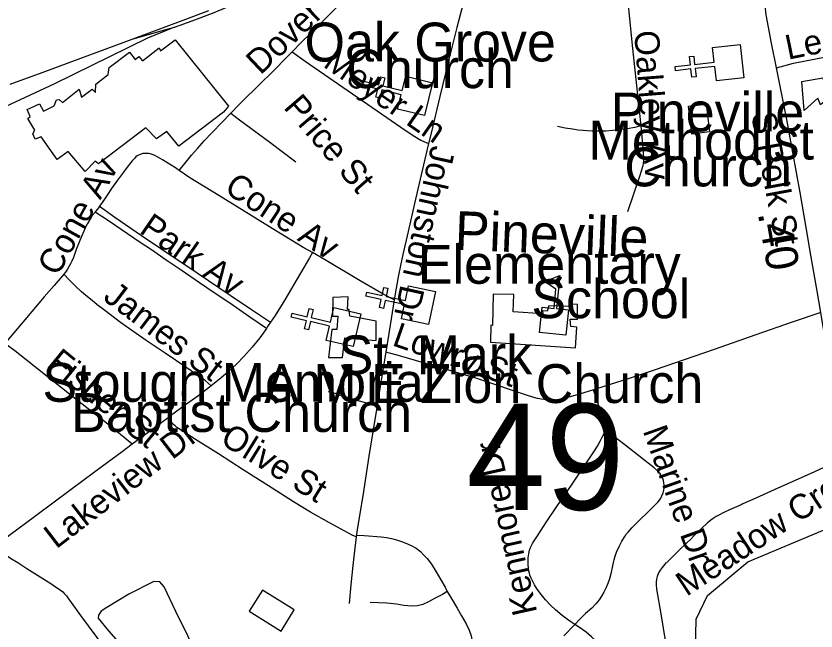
# Model space of a CAD drawing. Extents: x 1383679 to 1536984, y 460658 to 651027.
# Drawn here: x 1432722 to 1435810, y 488802 to 491178 of the extents above; entities that cross this region are included whole.
import ezdxf

# ---------------------------------------------------------------- set-up
doc = ezdxf.new("R2010")
doc.units = 0
for name, color, linetype in [('Exist Cultural Church CELL', 7, 'Continuous'), ('Exist Cultural Church Label', 7, 'Continuous'), ('Exist Cultural Educational Facility Elementary CELL', 7, 'Continuous'), ('Exist Cultural Educational Facility High Label', 7, 'Continuous'), ('Exist Cultural Warehouse Building Footprint', 7, 'Continuous'), ('Exist Hydrographic Creek Single Shore', 7, 'Continuous'), ('Exist Hydrographic Misc Water Feature', 7, 'Continuous'), ('Exist Railroad Mainline', 7, 'Continuous'), ('Exist Railroad Spur', 7, 'Continuous'), ('Exist Road Non-System Type 51', 7, 'Continuous'), ('Exist Road Non-System Type 51 Label', 7, 'Continuous'), ('Exist Road Secondary Mileage Hundredths English Label', 7, 'Continuous'), ('Exist Road Secondary Structure Standard Bridge Number Label', 7, 'Continuous'), ('Exist Road Secondary Type 51 Attributed', 7, 'Continuous'), ('Exist Road Secondary Type 51 Label', 7, 'Continuous')]:
    doc.layers.add(name, color=color, linetype=linetype)

msp = doc.modelspace()

# ---------------------------------------------------------------- linework, layer by layer
at = {"layer": 'Exist Cultural Church CELL'}
for points in [[(1435425.1, 490926.5), (1435418.7, 490983), (1435343, 490974.6), (1435346.5, 490942.8), (1435330.6, 490941.1), (1435327.1, 490972.9), (1435267.3, 490966.2), (1435265.6, 490982.2), (1435325.3, 490988.8), (1435321.8, 491020.6), (1435337.7, 491022.4), (1435341.2, 490990.6), (1435416.9, 490999), (1435410.6, 491056.3), (1435516.4, 491068), (1435530.9, 490938.2)], [(1434195, 490818.2), (1434208.4, 490873.6), (1434134.5, 490891.7), (1434126.9, 490860.6), (1434111.4, 490864.4), (1434119, 490895.5), (1434060.5, 490909.8), (1434064.3, 490925.3), (1434122.8, 490911), (1434130.4, 490942.1), (1434145.9, 490938.3), (1434138.3, 490907.2), (1434212.2, 490889.1), (1434226.1, 490945.1), (1434329.5, 490919.8), (1434298.4, 490792.9)], [(1434209.8, 490007.5), (1434221.4, 490063.2), (1434147, 490079), (1434140.3, 490047.7), (1434124.7, 490051), (1434131.3, 490082.3), (1434072.5, 490094.7), (1434075.8, 490110.4), (1434134.7, 490097.9), (1434141.3, 490129.3), (1434156.9, 490125.9), (1434150.3, 490094.6), (1434224.8, 490078.8), (1434236.8, 490135.2), (1434341, 490113.2), (1434313.9, 489985.4)], [(1433919.7, 489924.3), (1433932.4, 489979.8), (1433858.2, 489996.9), (1433851, 489965.7), (1433835.4, 489969.3), (1433842.6, 490000.5), (1433784, 490014), (1433787.6, 490029.6), (1433846.2, 490016.1), (1433853.4, 490047.3), (1433869, 490043.7), (1433861.8, 490012.5), (1433936, 489995.4), (1433949, 490051.5), (1434052.8, 490027.6), (1434023.4, 489900.3)]]:
    msp.add_lwpolyline(points, close=True, dxfattribs=at)
at = {"layer": 'Exist Cultural Educational Facility Elementary CELL'}
msp.add_lwpolyline([(1434743, 489955.3), (1434752.8, 490052.7), (1434798.6, 490048.1), (1434806, 490122.8), (1434761.6, 490151.6), (1434820.9, 490175), (1434808.1, 490047.2), (1434853.9, 490042.6), (1434844.2, 489945.1)], close=True, dxfattribs=at)
at = {"layer": 'Exist Cultural Warehouse Building Footprint'}
for points in [[(1433522.8, 490805.8), (1433350.2, 490674.6), (1433304.3, 490732), (1433264.5, 490702.7), (1433223.4, 490746.1), (1433041.1, 490606.7), (1433027.9, 490617.2), (1432989.2, 490576.3), (1432924, 490653.6), (1432880.6, 490623.1), (1432819, 490710.9), (1432796.1, 490701.6), (1432786.4, 490722.7), (1432794.8, 490736.7), (1432767.1, 490781.2), (1432776.7, 490789.4), (1432764.7, 490816.3), (1432813, 490838.6), (1432828.7, 490809.3), (1432869.7, 490830.4), (1432878.2, 490853.8), (1432889, 490855), (1432901.1, 490843.3), (1432966.3, 490894.8), (1432974.7, 490864.4), (1433015.8, 490894.8), (1433029.1, 490881.9), (1433030.3, 490913.6), (1433077.4, 490951), (1433081, 490979.1), (1433160.7, 491037.7), (1433182.4, 491009.6), (1433195.7, 491021.3), (1433210.2, 491004.9), (1433274.1, 491054.1), (1433280.2, 491043.6), (1433336.9, 491085.7), (1433542.2, 490829.2), (1433522.8, 490805.8)], [(1435755.1, 490924.1), (1435836, 490938.2), (1435854.1, 490857.3), (1435826.4, 490833.9), (1435816.7, 490859.7), (1435763.6, 490812.8), (1435755.1, 490924.1)], [(1435316.9, 490828.6), (1435385.5, 490837.3), (1435399, 490730.3), (1435330.3, 490721.6), (1435316.9, 490828.6)], [(1433945.4, 490090.8), (1433943, 490018.2), (1433964.7, 490018.2), (1433959.9, 489966.6), (1433940.6, 489966.6), (1433928.5, 489858.9), (1433981.6, 489858.9), (1433991.3, 489933.8), (1434112, 489924.5), (1434112, 489999.4), (1434010.6, 490018.2), (1434008.2, 490043.9), (1434000.9, 490043.9), (1434003.4, 490093.1), (1433945.4, 490090.8)], [(1434563.5, 490103.7), (1434561.1, 489981.9), (1434555.1, 489983), (1434553.9, 489917.5), (1434881.1, 489896.4), (1434885.9, 489976), (1434862.9, 489978.4), (1434860.5, 490006.5), (1434889.5, 490006.5), (1434889.5, 490062.7), (1434858.1, 490065), (1434859.3, 490055.7), (1434778.4, 490058), (1434772.4, 490036.9), (1434754.3, 490038.1), (1434755.5, 490027.5), (1434640.8, 490034.6), (1434643.2, 490101.3), (1434563.5, 490103.7)], [(1433672.8, 488960.1), (1433622.2, 488878.3), (1433745.6, 488802), (1433796.2, 488883.8), (1433672.8, 488960.1)]]:
    msp.add_lwpolyline(points, dxfattribs=at)
at = {"layer": 'Exist Hydrographic Creek Single Shore'}
msp.add_lwpolyline([(1434883.2, 488225.5), (1435151.1, 488184.9), (1435265.1, 488067.7), (1435441.2, 487680.1), (1435581.2, 487575.6), (1435723.2, 487615.3), (1435892.2, 487720.3), (1436056.2, 488009.1), (1436102.1, 488257.7), (1436054.2, 488350.6), (1435947.1, 488428.2), (1435434.2, 488596.1), (1435343.1, 488666.8), (1435347.5, 488848), (1435390.5, 488939), (1435547, 489069.3), (1435834.2, 489189.9), (1436016.8, 489200.4), (1436155, 489208.7)], dxfattribs=at)
at = {"layer": 'Exist Hydrographic Misc Water Feature'}
msp.add_lwpolyline([(1433432.8, 488687.2), (1433338.5, 488877), (1433294.2, 488972.3), (1433276.6, 488992.3), (1433254.6, 488992.8), (1433157.6, 488944.6), (1433072.6, 488892.2), (1433050.4, 488878.7), (1433040, 488863.3), (1433039.7, 488851), (1433078.9, 488802.6), (1433155.2, 488716.6)], dxfattribs=at)
at = {"layer": 'Exist Railroad Mainline'}
for points in [[(1433170.1, 491088.3), (1433367.4, 491161.9), (1433466, 491198.7)], [(1432699.7, 490913.9), (1432837.3, 490964.7), (1432972.9, 491015.2), (1433170.1, 491088.3)]]:
    msp.add_lwpolyline(points, dxfattribs=at)
at = {"layer": 'Exist Railroad Spur'}
for points in [[(1433333.8, 491134.7), (1433402, 491158.7), (1433479.9, 491188.9), (1433518.2, 491204.1), (1433578.5, 491229.2), (1433654.1, 491263.6), (1433725.7, 491297.7), (1433772.5, 491321.1), (1433820, 491345.9), (1433876.4, 491377.9), (1433955, 491424.3), (1434018.1, 491465.2), (1434098.9, 491519.4), (1434172.7, 491573.1), (1434181.6, 491579.7)], [(1433333.8, 491134.7), (1433229.3, 491091.6), (1432871.2, 490915), (1432682.9, 490828.4), (1432475, 490729.8), (1432156.3, 490582.2)], [(1433170.1, 491088.3), (1433300.8, 491125.1), (1433333.8, 491134.7)]]:
    msp.add_lwpolyline(points, dxfattribs=at)
at = {"layer": 'Exist Road Non-System Type 51'}
msp.add_line((1434879.1, 488827.6), (1434836.9, 488782.9), dxfattribs=at)
for points in [[(1433787.4, 491039.6), (1433822.4, 491074.7), (1433860.6, 491112.8), (1433895.5, 491147.4), (1433929.6, 491181), (1433959.6, 491210.9), (1434035.1, 491285.9), (1434141.1, 491395.1), (1434205.7, 491464.9), (1434237, 491500), (1434252.2, 491520.4), (1434270.7, 491546.9)], [(1434519.2, 491472), (1434507.1, 491433.5), (1434491, 491382.3), (1434454.1, 491251.1), (1434423.6, 491132.9), (1434391.5, 491004.1), (1434357.8, 490866.1), (1434324.2, 490725.5), (1434314.6, 490684.9)], [(1435073.8, 491333), (1435079, 491272.4), (1435087, 491193.8), (1435099.9, 491063.3), (1435124.7, 490837.5), (1435133.5, 490752.8)], [(1435656.7, 490977.6), (1435722.9, 490994.7), (1435808.9, 491012.6), (1435878.6, 491026.4), (1435970.3, 491044.2), (1436089.5, 491071), (1436145.4, 491085.6), (1436215.2, 491100.2), (1436247.5, 491106.7), (1436270.5, 491111.3), (1436291.7, 491114.6)], [(1433551.6, 490802.1), (1433583.6, 490835.6), (1433671.4, 490921.5), (1433705.2, 490955.7), (1433777.1, 491029.3), (1433787.4, 491039.6)], [(1433787.4, 491039.6), (1433838.1, 491002.5), (1434020.5, 490876.3), (1434227.8, 490733.5), (1434261.4, 490712.3), (1434284.6, 490698.5), (1434298.2, 490691.7), (1434314.6, 490684.9)], [(1433352.2, 490580.6), (1433378.3, 490614), (1433399.2, 490639.7), (1433422.2, 490666), (1433449.3, 490696.1), (1433476.8, 490724.8), (1433519.3, 490768.1), (1433551.6, 490802.1)], [(1433551.6, 490802.1), (1433584.4, 490777), (1433701.8, 490690.2), (1433802.6, 490614.7)], [(1435133.5, 490752.8), (1435128.4, 490751.4), (1435110.4, 490747.1), (1435081.1, 490741.7), (1435053, 490737.6), (1435025.8, 490734.6), (1434998.8, 490732.9), (1434970, 490732.2), (1434945.8, 490732.7), (1434926.4, 490733.6), (1434911, 490734.7), (1434891.4, 490736.9), (1434869.4, 490740.2), (1434841.6, 490744.8), (1434812.2, 490750.1)], [(1435133.5, 490752.8), (1435136.3, 490725.5), (1435141.7, 490666.4), (1435143.1, 490647.2), (1435143.9, 490632.7), (1435144.1, 490622.8), (1435143.5, 490615.1), (1435142.7, 490608.6), (1435140.7, 490598.9), (1435135, 490578.5), (1435128.4, 490557.7), (1435082, 490421.7)], [(1434314.6, 490684.9), (1434295, 490602), (1434260.4, 490453.4), (1434235.5, 490345.7), (1434215.5, 490256.9), (1434206.1, 490213.5), (1434198.8, 490176.7), (1434189.4, 490126.1), (1434181.8, 490080.8)], [(1433352.2, 490580.6), (1433337.6, 490590.5), (1433287, 490621.4), (1433270, 490632), (1433260.8, 490636.8), (1433251.4, 490641), (1433240.5, 490644.7), (1433235.1, 490645.8), (1433225.9, 490646.6), (1433217.8, 490646.6), (1433211.8, 490645.8), (1433204.5, 490644), (1433197.5, 490641.1), (1433190.2, 490637), (1433184.6, 490633.1), (1433180.1, 490628.8), (1433170, 490618.1), (1433164.7, 490611.9), (1433151.2, 490594.2), (1433136.9, 490574.9), (1433113.5, 490543.4), (1433090.9, 490511.4), (1433073.7, 490485.1), (1433066.2, 490473.6), (1433054.9, 490457.7), (1433044.8, 490443.6)], [(1433866.3, 490263.4), (1433833, 490282.3), (1433726.8, 490345.8), (1433504.3, 490484.4), (1433393.5, 490552.6), (1433352.2, 490580.6)], [(1433044.8, 490443.6), (1433039.9, 490436.9), (1433027.9, 490421.3), (1433027, 490420.1)], [(1433044.8, 490443.6), (1433103.5, 490400.6), (1433205.8, 490329.9), (1433280.7, 490279.1), (1433421.3, 490185.7), (1433548.6, 490098.6), (1433631, 490043.6), (1433704.8, 489994.9)], [(1433027, 490420.1), (1433016.6, 490406.3), (1433011.6, 490399), (1433006.5, 490391.5), (1432997.5, 490376.3), (1432992.8, 490367.4), (1432988.5, 490358.2), (1432974.6, 490325.2), (1432965.9, 490303.8), (1432954.9, 490275.3), (1432943.4, 490244.8), (1432937.4, 490230.3), (1432932.7, 490220.4), (1432927.5, 490210.8), (1432920.7, 490199.4), (1432913.2, 490187.9), (1432907, 490180)], [(1433688.3, 489970.9), (1433624.7, 490013.8), (1433547, 490068), (1433487.5, 490108.5), (1433429.9, 490147), (1433359.5, 490195.3), (1433301.5, 490234.8), (1433244.7, 490274.1), (1433201.5, 490303.1), (1433078.6, 490386.7), (1433027, 490420.1)], [(1433866.3, 490263.4), (1433854.8, 490243), (1433820.6, 490184.6), (1433759, 490081.5), (1433722.2, 490020.5), (1433704.8, 489994.9)], [(1434181.8, 490080.8), (1434142, 490101.3), (1434050.5, 490155.2), (1433919.3, 490233.2), (1433866.3, 490263.4)], [(1432907, 490180), (1432901.9, 490173.5), (1432870, 490137.1), (1432830.9, 490092.5), (1432756.3, 490004.2), (1432699.7, 489937.5), (1432679.5, 489912.8)], [(1433475.4, 489748.7), (1433463.7, 489759.3), (1433451.6, 489769.3), (1433444.7, 489774.7), (1433381.4, 489818), (1433298.1, 489874.6), (1433224.1, 489924.4), (1433172.4, 489960.2), (1433125.7, 489993.9), (1433065.4, 490039.6), (1433035.9, 490061.9), (1433015.6, 490078.1), (1432992.2, 490097.4), (1432975.1, 490112.5), (1432952.3, 490133.4), (1432927.5, 490158.7), (1432907, 490180)], [(1434181.8, 490080.8), (1434165.5, 489982.8), (1434148.9, 489879.5)], [(1435828.3, 490032.2), (1435717.3, 489994.8), (1435577.1, 489945.6), (1435416.2, 489889.9), (1435184.7, 489809.3), (1435085.1, 489776.2), (1434994.3, 489747.1), (1434950.6, 489733.5)], [(1433704.8, 489994.9), (1433693.1, 489977.8), (1433688.3, 489970.9)], [(1433688.3, 489970.9), (1433662.8, 489934.3), (1433633.2, 489898.6), (1433600.8, 489861.8), (1433574.3, 489833.6), (1433572.9, 489832.2), (1433541.3, 489802.8), (1433512.8, 489778), (1433475.4, 489748.7)], [(1433170.9, 489523.4), (1433139.1, 489549.7), (1433069.9, 489606.1), (1432977.9, 489677.8), (1432848.3, 489780.4), (1432717, 489883.9), (1432679.5, 489912.8)], [(1434148.9, 489879.5), (1434140.4, 489826.4), (1434127.9, 489745.8), (1434121.5, 489705), (1434116.3, 489673.6)], [(1434950.6, 489733.5), (1434897, 489716.8), (1434856.2, 489705.7), (1434833.4, 489699.8), (1434816.2, 489696.3), (1434800.7, 489694.2), (1434788.3, 489693.5), (1434782.3, 489693.4), (1434767.8, 489694.5), (1434750.8, 489697), (1434735.1, 489700.1), (1434720.7, 489704.1), (1434691.8, 489713.1), (1434646.3, 489728.8), (1434565.8, 489755.9), (1434496.1, 489778.6), (1434364.9, 489817.2), (1434201.8, 489865.5), (1434148.9, 489879.5)], [(1433475.4, 489748.7), (1433469.4, 489744), (1433427.6, 489712.2), (1433376.2, 489675.2), (1433318.9, 489633.3), (1433308.9, 489625.8)], [(1433927.2, 489726.8), (1433937.1, 489724.9), (1433944.1, 489723.3), (1433953.5, 489720.4), (1433974.6, 489713.5), (1434005.5, 489703.4), (1434031.7, 489695.4), (1434074.2, 489683.6), (1434103.1, 489676.5), (1434116.3, 489673.6)], [(1435002.5, 489583.9), (1435000.1, 489587.7), (1434995.6, 489596.1), (1434993.4, 489601.3), (1434990.6, 489609.6), (1434985.5, 489626.8), (1434982, 489637.8), (1434967.1, 489683.5), (1434950.6, 489733.5)], [(1434116.3, 489673.6), (1434101.8, 489586.7), (1434084.2, 489476.7), (1434060.4, 489323.8), (1434040.4, 489201.8), (1434035.5, 489166.2)], [(1433308.9, 489625.8), (1433250.9, 489582.6), (1433170.9, 489523.4)], [(1434035.5, 489166.2), (1434019.7, 489172.8), (1433990.7, 489187.8), (1433932.4, 489220.1), (1433859.2, 489261.2), (1433792.9, 489300.5), (1433711, 489353.4), (1433598.8, 489424.8), (1433503.2, 489486.1), (1433414.9, 489542.2), (1433384.6, 489561.5), (1433348.9, 489584.5), (1433342.9, 489588.6), (1433336.4, 489593.9), (1433329.9, 489599.9), (1433321.4, 489609.7), (1433308.9, 489625.8)], [(1434879.1, 488827.6), (1434879, 488827.7), (1434863, 488837.2), (1434850, 488846.3), (1434830.5, 488862), (1434804.6, 488883.7), (1434785.9, 488900.9), (1434765.3, 488922.6), (1434750, 488941.3), (1434733.6, 488963.8), (1434722.9, 488980.6), (1434714.9, 488995.9), (1434710.3, 489005.8), (1434705.7, 489018), (1434703.4, 489025.3), (1434701.5, 489033.7), (1434699.5, 489046.3), (1434698.5, 489058.1), (1434698.2, 489066), (1434699.1, 489083), (1434700.1, 489093.6), (1434700.8, 489098.2), (1434702.6, 489107.5), (1434704.4, 489114.4), (1434707.7, 489124), (1434711.1, 489132), (1434715.5, 489140.3), (1434719.8, 489147), (1434734.8, 489170.2), (1434769.4, 489223.2), (1434809.9, 489283.4), (1434868.7, 489369.5), (1434920.9, 489447.1), (1434952.4, 489494.3), (1434965.8, 489515.4), (1434976.5, 489534.7), (1434984.8, 489550.5), (1435002.5, 489583.9)], [(1435028, 489066), (1435030.3, 489076.3), (1435034.4, 489091.2), (1435040, 489106.8), (1435049.9, 489128.6), (1435060.4, 489148.4), (1435072, 489167.5), (1435077.5, 489175.5), (1435084.2, 489184.3), (1435098.7, 489200.3), (1435126.2, 489227.8), (1435162.9, 489264.2), (1435189.8, 489290.3), (1435198.9, 489300.2), (1435206.5, 489308.8), (1435211, 489315.7), (1435215.2, 489324.4), (1435219.1, 489335.1), (1435221.7, 489345.5), (1435223.2, 489353.5), (1435223.6, 489360.1), (1435223.3, 489366.2), (1435222.2, 489374.4), (1435220.4, 489382.7), (1435218, 489390.5), (1435215, 489397.5), (1435211, 489404.7), (1435206.3, 489411.2), (1435199.3, 489418.8), (1435184.8, 489431.8), (1435162.1, 489450.3), (1435126.4, 489478.5), (1435072.1, 489520.9), (1435044.2, 489542.1), (1435027, 489555.3), (1435017.9, 489563.7), (1435013.4, 489569.1), (1435005.8, 489578.7), (1435002.5, 489583.9)], [(1433170.9, 489523.4), (1433131.7, 489494.3), (1433054.9, 489436.8), (1432984.9, 489386.3), (1432874.7, 489303.3), (1432794.1, 489242.5), (1432699.8, 489173.9), (1432640.6, 489128.7)], [(1435854.4, 489439.4), (1435789.1, 489410.5), (1435648.4, 489347.9), (1435577.1, 489315.1), (1435527.5, 489292.8), (1435520.5, 489289.6), (1435476.3, 489269.9), (1435453.7, 489259.3), (1435434.4, 489249.8), (1435424, 489243.8), (1435409.1, 489234), (1435391.2, 489219.8), (1435368.1, 489198.4), (1435333.3, 489164.5), (1435331.2, 489162.4), (1435283.4, 489115.3), (1435234.2, 489066)], [(1434035.5, 489166.2), (1434029.5, 489122.2), (1434023.6, 489066), (1434022.5, 489054.7), (1434014.9, 488980.2), (1434007.8, 488907.6)], [(1434036.2, 489171.8), (1434066.2, 489170.3), (1434130.9, 489165.8), (1434151.4, 489163), (1434171.8, 489159.2), (1434191.1, 489154.2), (1434209.4, 489148.2), (1434226.6, 489141.9), (1434247.6, 489132.1), (1434265.9, 489121.7), (1434283.1, 489108.7), (1434295.4, 489096.5), (1434308.4, 489081.8), (1434326.1, 489060), (1434343.5, 489030.7), (1434362.1, 488999.3), (1434377.9, 488970.7), (1434386.5, 488955.1)], [(1432640.6, 489128.7), (1432641.3, 489127.8), (1432645.5, 489123.6), (1432654, 489115.4), (1432664, 489107.6), (1432681.1, 489096.3), (1432707.8, 489079.2), (1432728.8, 489066), (1432764.5, 489043.6), (1432855.9, 488985), (1432882.7, 488967.9), (1432893.1, 488960.4), (1432902.2, 488953), (1432909.7, 488945.8), (1432916.9, 488937.7), (1432922.5, 488929.7), (1432971.6, 488861.3), (1433063.9, 488737)], [(1435026.8, 489066), (1435024.2, 489053.1), (1435017.7, 489023.4), (1435012.1, 489003.3), (1435006.2, 488986), (1434999.8, 488970.4), (1434990.9, 488951.6), (1434982.3, 488937.2), (1434972.2, 488922.4), (1434959.6, 488907.4), (1434944, 488890.8), (1434920, 488869), (1434898.3, 488847.8), (1434879.1, 488827.6)], [(1435231.9, 489066), (1435215.9, 489047.2), (1435207.9, 489036.6), (1435201.7, 489026.1), (1435196.1, 489012.8), (1435193.4, 489002.1), (1435192.3, 488991), (1435192.4, 488981.1), (1435194.3, 488963.4), (1435210.5, 488867.8), (1435236.1, 488710.6)], [(1434386.5, 488955.1), (1434367.6, 488943.5), (1434337, 488927.3), (1434313.6, 488915.2), (1434292.8, 488904.8), (1434271.9, 488898.7), (1434250.2, 488897.8), (1434219, 488900.4), (1434190.4, 488905.6), (1434153, 488909.1), (1434088.9, 488912.6)], [(1434386.5, 488955.1), (1434404.6, 488925.6), (1434424.6, 488890), (1434441.1, 488860.5), (1434459.4, 488830.1), (1434471.5, 488804.9), (1434478.5, 488783.2), (1434481.1, 488769.3), (1434481.9, 488741.6), (1434484.6, 488682.6)], [(1435017, 488676.2), (1435004.9, 488699.1), (1434990.5, 488723.6), (1434976.5, 488744.2), (1434960.1, 488763.7), (1434943.3, 488780), (1434922.6, 488797.6), (1434910.1, 488806.6), (1434896.9, 488815.9), (1434879.1, 488827.6)]]:
    msp.add_lwpolyline(points, dxfattribs=at)
at = {"layer": 'Exist Road Secondary Type 51 Attributed'}
msp.add_lwpolyline([(1436016.8, 489200.4), (1435978.6, 489347.1), (1435957, 489436), (1435951.3, 489460.9), (1435943.6, 489494.4), (1435937.7, 489520.1), (1435908.7, 489636.2), (1435898.2, 489678.4), (1435883.6, 489736.6), (1435868.6, 489808.7), (1435850.3, 489903.1), (1435835.2, 489992), (1435828.3, 490032.2), (1435812.8, 490122.6), (1435789.3, 490253.6), (1435771, 490360.1), (1435748.2, 490495.3), (1435720.5, 490650.5), (1435697.2, 490778.3), (1435656.7, 490977.6), (1435637.4, 491072.6), (1435617.8, 491182.2), (1435609.3, 491255.7), (1435603.1, 491303)], dxfattribs=at)

# ---------------------------------------------------------------- texts
at = {"layer": 'Exist Cultural Church Label'}
for s, p in [('Oak Grove', (1433835.8, 491001.9)), ('Church', (1433996.9, 490898.9)), ('Pineville', (1435017, 490732)), ('Methodist', (1434931.8, 490623)), ('Church', (1435069.9, 490519.5)), ('St. Mark', (1433967.4, 489793.9)), ('Stough Memorial', (1432824.3, 489687.4)), ('A M E Zion Church', (1433680, 489682.7)), ('Baptist Church', (1432934.8, 489570.9))]:
    msp.add_text(s, height=150, rotation=0, dxfattribs=at).set_placement(p)
at = {"layer": 'Exist Cultural Educational Facility High Label'}
for s, rotation, p in [('Pineville', 357.7957, (1434413.4, 490274.4)), ('Elementary', 0, (1434273, 490143.2)), ('School', 0, (1434711.1, 490010.2))]:
    msp.add_text(s, height=150, rotation=rotation, dxfattribs=at).set_placement(p)
at = {"layer": 'Exist Road Non-System Type 51 Label'}
for s, rotation, p in [('Dover St', 43.4188, (1433665.5, 490947)), ('Lee St', 11.4921, (1435701.5, 491008.4)), ('Oakley Av', 274.4367, (1435107.7, 491118.5)), ('Meyer Ln', 325.1832, (1433903.1, 490984.1)), ('Price St', 310.7117, (1433751.4, 490823.3)), ('Johnston Dr', 257.6127, (1434325, 490681)), ('Cone Av', 60.9421, (1432882.7, 490168.7)), ('Cone Av', 326.595, (1433521.1, 490499.8)), ('Park Av', 325.4465, (1433193.9, 490342.8)), ('James St', 322.7893, (1433053.9, 490083.5)), ('Lowry St', 340.7643, (1434169.8, 489906.5)), ('Fisher St', 320.5986, (1432836.3, 489826.6)), ('Lakeview Dr', 37.5787, (1432877.1, 489116.7)), ('Olive St', 328.2935, (1433505.4, 489528.8)), ('Marine Dr', 289.7265, (1435140.2, 489575.5)), ('Kenmore Dr', 102.5798, (1434734.1, 488874.3)), ('Meadow Creek Ln', 33.5041, (1435310, 488933.4))]:
    msp.add_text(s, height=95, rotation=rotation, dxfattribs=at).set_placement(p)
at = {"layer": 'Exist Road Secondary Mileage Hundredths English Label'}
msp.add_text('.40', height=125, rotation=279.7521, dxfattribs=at).set_placement((1435584.6, 490415.8))
at = {"layer": 'Exist Road Secondary Structure Standard Bridge Number Label'}
msp.add_text('49', height=410.1, dxfattribs=at).set_placement((1434460.4, 489269.7))
at = {"layer": 'Exist Road Secondary Type 51 Label'}
msp.add_text('S Polk St', height=95, rotation=280.5378, dxfattribs=at).set_placement((1435559, 490798.4))

doc.saveas('drawing.dxf')
